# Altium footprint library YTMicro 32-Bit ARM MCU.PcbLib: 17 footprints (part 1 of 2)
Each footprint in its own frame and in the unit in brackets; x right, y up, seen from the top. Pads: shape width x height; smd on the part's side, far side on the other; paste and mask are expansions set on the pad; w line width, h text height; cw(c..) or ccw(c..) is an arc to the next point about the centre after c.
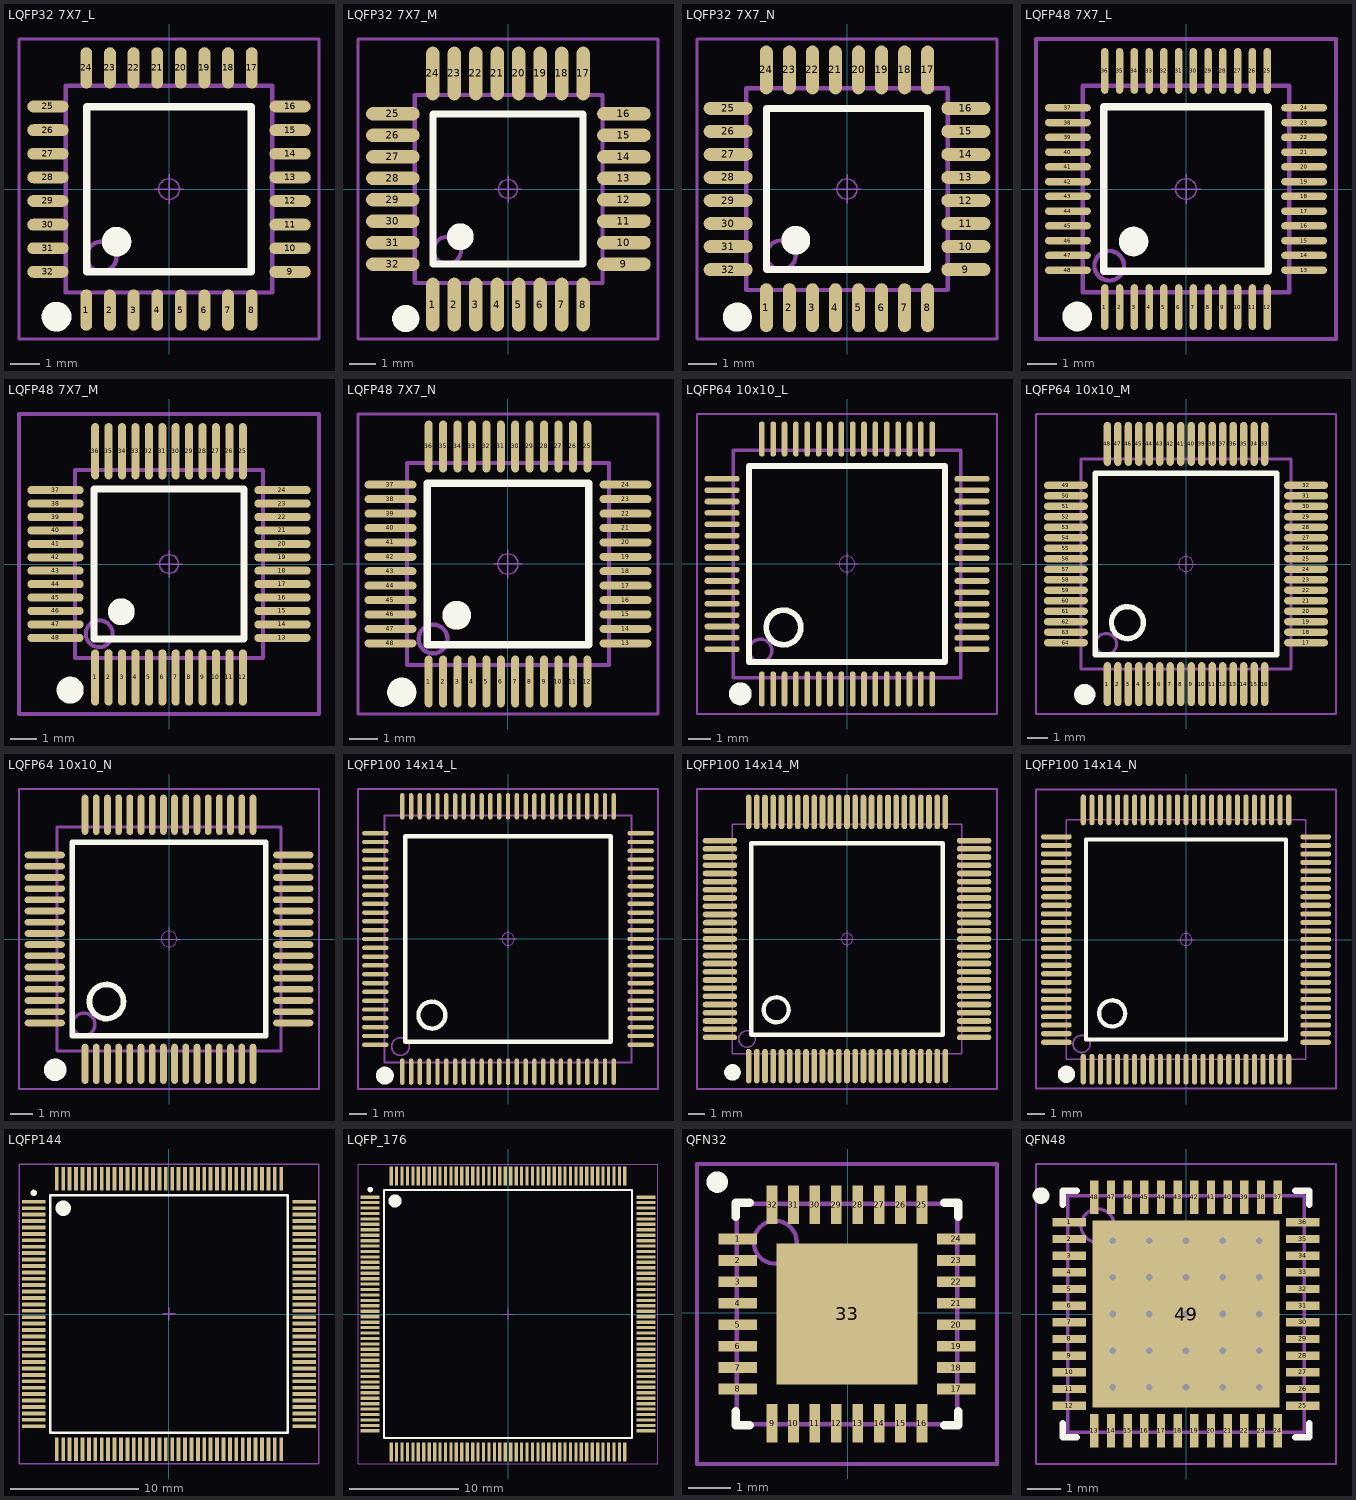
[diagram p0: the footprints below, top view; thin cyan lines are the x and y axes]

## LQFP32 7X7_L [mm]
pads (32):
  oval 0.4x1.4 smd: 1(-2.8,-4.096) 2(-2,-4.096) 3(-1.2,-4.096) 4(-0.4,-4.096) 5(0.4,-4.096) 6(1.2,-4.096) 7(2,-4.096) 8(2.8,-4.096) 17(2.8,4.108) 18(2,4.108) 19(1.2,4.108) 20(0.4,4.108) 21(-0.4,4.108) 22(-1.2,4.108) 23(-2,4.108) 24(-2.8,4.108)
  oval 1.4x0.4 smd: 9(4.102,-2.8) 10(4.102,-2) 11(4.102,-1.2) 12(4.102,-0.4) 13(4.102,0.4) 14(4.102,1.2) 15(4.102,2) 16(4.102,2.8) 25(-4.102,2.8) 26(-4.102,2) 27(-4.102,1.2) 28(-4.102,0.4) 29(-4.102,-0.4) 30(-4.102,-1.2) 31(-4.102,-2) 32(-4.102,-2.8)
Top Overlay:
  circle w0.508: c-3.81,-4.318 r0.25
  circle w0.5: c-1.778,-1.778 r0.25
  lines w0.254: -2.794,-2.794 -2.794,2.794 2.794,2.794 2.794,-2.794 -2.794,-2.794
Mechanical 13:
  circle w0.15: c-2.286,-2.286 r0.508
  lines w0.15: -3.5,-3.5 3.5,-3.5 3.5,3.5 -3.5,3.5 -3.5,-3.5
Mechanical 15:
  circle w0.05: c0,0 r0.35
  lines w0.05: -0.5,0 0.5,0 ; 0,-0.5 0,0.5
  lines w0.1: -5.08,-5.074 5.08,-5.074 5.08,5.086 -5.08,5.086 -5.08,-5.074
3D body "LQFP32-7x7.STEP": height 1.45, standoff 0, extent -4.503,-4.503 4.503,4.503

## LQFP32 7X7_M [mm]
pads (32):
  oval 0.5x2 smd: 1(-2.8,-4.303) 2(-2,-4.303) 3(-1.2,-4.303) 4(-0.4,-4.303) 5(0.4,-4.303) 6(1.2,-4.303) 7(2,-4.303) 8(2.8,-4.303) 17(2.8,4.303) 18(2,4.303) 19(1.2,4.303) 20(0.4,4.303) 21(-0.4,4.303) 22(-1.2,4.303) 23(-2,4.303) 24(-2.8,4.303)
  oval 2x0.5 smd: 9(4.317,-2.8) 10(4.317,-2) 11(4.317,-1.2) 12(4.317,-0.4) 13(4.317,0.4) 14(4.317,1.2) 15(4.317,2) 16(4.317,2.8) 25(-4.289,2.8) 26(-4.289,2) 27(-4.289,1.2) 28(-4.289,0.4) 29(-4.289,-0.4) 30(-4.289,-1.2) 31(-4.289,-2) 32(-4.289,-2.8)
Top Overlay:
  circle w0.5: c-1.778,-1.778 r0.25
  circle w0.508: c-3.81,-4.826 r0.25
  lines w0.254: -2.794,-2.794 2.794,-2.794 2.794,2.794 -2.794,2.794 -2.794,-2.794
Mechanical 13:
  circle w0.15: c-2.26,-2.286 r0.508
  lines w0.15: -3.474,-3.5 3.526,-3.5 3.526,3.5 -3.474,3.5 -3.474,-3.5
Mechanical 15:
  circle w0.05: c0,0 r0.35
  lines w0.05: -0.5,0 0.5,0 ; 0,-0.5 0,0.5
  lines w0.1: -5.588,-5.588 5.588,-5.588 5.588,5.588 -5.588,5.588 -5.588,-5.588
3D body "LQFP32-7x7.STEP": height 1.45, standoff 0, extent -4.503,-4.503 4.503,4.503

## LQFP32 7X7_N [mm]
pads (32):
  oval 0.45x1.7 smd: 1(-2.8,-4.12) 2(-2,-4.12) 3(-1.2,-4.12) 4(-0.4,-4.12) 5(0.4,-4.12) 6(1.2,-4.12) 7(2,-4.12) 8(2.8,-4.12) 17(2.8,4.132) 18(2,4.132) 19(1.2,4.132) 20(0.4,4.132) 21(-0.4,4.132) 22(-1.2,4.132) 23(-2,4.132) 24(-2.8,4.132)
  oval 1.7x0.45 smd: 9(4.126,-2.8) 10(4.126,-2) 11(4.126,-1.2) 12(4.126,-0.4) 13(4.126,0.4) 14(4.126,1.2) 15(4.126,2) 16(4.126,2.8) 25(-4.126,2.8) 26(-4.126,2) 27(-4.126,1.2) 28(-4.126,0.4) 29(-4.126,-0.4) 30(-4.126,-1.2) 31(-4.126,-2) 32(-4.126,-2.8)
Top Overlay:
  circle w0.5: c-1.778,-1.778 r0.25
  circle w0.508: c-3.81,-4.445 r0.25
  lines w0.254: -2.794,-2.794 2.794,-2.794 2.794,2.794 -2.794,2.794 -2.794,-2.794
Mechanical 13:
  circle w0.15: c-2.286,-2.292 r0.508
  lines w0.15: -3.5,-3.506 -3.5,3.494 3.5,3.494 3.5,-3.506 -3.5,-3.506
Mechanical 15:
  circle w0.05: c0,0 r0.35
  lines w0.05: -0.5,0 0.5,0 ; 0,-0.5 0,0.5
  lines w0.1: -5.207,-5.207 -5.207,5.207 5.207,5.207 5.207,-5.207 -5.207,-5.207
3D body "LQFP32-7x7.STEP": height 1.45, standoff 0, extent -4.503,-4.503 4.503,4.503

## LQFP48 7X7_L [mm]
height 1.6
pads (48):
  oval 0.25x1.55 smd: 1(-2.75,-4) 2(-2.25,-4) 3(-1.75,-4) 4(-1.25,-4) 5(-0.75,-4) 6(-0.25,-4) 7(0.25,-4) 8(0.75,-4) 9(1.25,-4) 10(1.75,-4) 11(2.25,-4) 12(2.75,-4) 25(2.75,4) 26(2.25,4) 27(1.75,4) 28(1.25,4) 29(0.75,4) 30(0.25,4) 31(-0.25,4) 32(-0.75,4) 33(-1.25,4) 34(-1.75,4) 35(-2.25,4) 36(-2.75,4)
  oval 1.55x0.25 smd: 13(4,-2.75) 14(4,-2.25) 15(4,-1.75) 16(4,-1.25) 17(4,-0.75) 18(4,-0.25) 19(4,0.25) 20(4,0.75) 21(4,1.25) 22(4,1.75) 23(4,2.25) 24(4,2.75) 37(-4,2.75) 38(-4,2.25) 39(-4,1.75) 40(-4,1.25) 41(-4,0.75) 42(-4,0.25) 43(-4,-0.25) 44(-4,-0.75) 45(-4,-1.25) 46(-4,-1.75) 47(-4,-2.25) 48(-4,-2.75)
Top Overlay:
  circle w0.508: c-3.683,-4.318 r0.25
  circle w0.5: c-1.778,-1.778 r0.25
  lines w0.254: -2.794,-2.794 -2.794,2.794 2.794,2.794 2.794,-2.794 -2.794,-2.794
Mechanical 13:
  circle w0.15: c-2.6,-2.6 r0.5
  lines w0.15: -3.5,-3.5 -3.5,3.5 3.5,3.5 3.5,-3.5 -3.5,-3.5
Mechanical 15:
  circle w0.05: c0,0 r0.35
  lines w0.05: -0.5,0 0.5,0 ; 0,-0.5 0,0.5
  lines w0.15: -5.08,-5.08 -5.08,5.08 5.08,5.08 5.08,-5.08 -5.08,-5.08
3D body "LQFP48-7x7.STEP": height 1.45, standoff 0, extent -4.503,-4.503 4.503,4.503

## LQFP48 7X7_M [mm]
height 1.6
pads (48):
  oval 0.3x2.1 smd: 1(-2.75,-4.227) 2(-2.25,-4.227) 3(-1.75,-4.227) 4(-1.25,-4.227) 5(-0.75,-4.227) 6(-0.25,-4.227) 7(0.25,-4.227) 8(0.75,-4.227) 9(1.25,-4.227) 10(1.75,-4.227) 11(2.25,-4.227) 12(2.75,-4.227) 25(2.75,4.202) 26(2.25,4.202) 27(1.75,4.202) 28(1.25,4.202) 29(0.75,4.202) 30(0.25,4.202) 31(-0.25,4.202) 32(-0.75,4.202) 33(-1.25,4.202) 34(-1.75,4.202) 35(-2.25,4.202) 36(-2.75,4.202)
  oval 2.1x0.3 smd: 13(4.227,-2.75) 14(4.227,-2.25) 15(4.227,-1.75) 16(4.227,-1.25) 17(4.227,-0.75) 18(4.227,-0.25) 19(4.227,0.25) 20(4.227,0.75) 21(4.227,1.25) 22(4.227,1.75) 23(4.227,2.25) 24(4.227,2.75) 37(-4.227,2.75) 38(-4.227,2.25) 39(-4.227,1.75) 40(-4.227,1.25) 41(-4.227,0.75) 42(-4.227,0.25) 43(-4.227,-0.25) 44(-4.227,-0.75) 45(-4.227,-1.25) 46(-4.227,-1.75) 47(-4.227,-2.25) 48(-4.227,-2.75)
Top Overlay:
  circle w0.5: c-1.778,-1.778 r0.25
  circle w0.508: c-3.683,-4.699 r0.25
  lines w0.254: -2.794,-2.794 2.794,-2.794 2.794,2.794 -2.794,2.794 -2.794,-2.794
Mechanical 13:
  circle w0.15: c-2.6,-2.6 r0.5
  lines w0.15: -3.5,-3.5 -3.5,3.5 3.5,3.5 3.5,-3.5 -3.5,-3.5
Mechanical 15:
  circle w0.05: c0,0 r0.35
  lines w0.05: -0.5,0 0.5,0 ; 0,-0.5 0,0.5
  lines w0.15: -5.588,-5.588 -5.588,5.588 5.588,5.588 5.588,-5.588 -5.588,-5.588
3D body "LQFP48-7x7.STEP": height 1.45, standoff 0, extent -4.503,-4.503 4.503,4.503

## LQFP48 7X7_N [mm]
height 1.6
pads (48):
  oval 0.279x1.8 smd: 1(-2.75,-4.075) 2(-2.25,-4.075) 3(-1.75,-4.075) 4(-1.25,-4.075) 5(-0.75,-4.075) 6(-0.25,-4.075) 7(0.25,-4.075) 8(0.75,-4.075) 9(1.25,-4.075) 10(1.75,-4.075) 11(2.25,-4.075) 12(2.75,-4.075) 25(2.75,4.075) 26(2.25,4.075) 27(1.75,4.075) 28(1.25,4.075) 29(0.75,4.075) 30(0.25,4.075) 31(-0.25,4.075) 32(-0.75,4.075) 33(-1.25,4.075) 34(-1.75,4.075) 35(-2.25,4.075) 36(-2.75,4.075)
  oval 1.8x0.279 smd: 13(4.075,-2.75) 14(4.075,-2.25) 15(4.075,-1.75) 16(4.075,-1.25) 17(4.075,-0.75) 18(4.075,-0.25) 19(4.075,0.25) 20(4.075,0.75) 21(4.075,1.25) 22(4.075,1.75) 23(4.075,2.25) 24(4.075,2.75) 37(-4.075,2.75) 38(-4.075,2.25) 39(-4.075,1.75) 40(-4.075,1.25) 41(-4.075,0.75) 42(-4.075,0.25) 43(-4.075,-0.25) 44(-4.075,-0.75) 45(-4.075,-1.25) 46(-4.075,-1.75) 47(-4.075,-2.25) 48(-4.075,-2.75)
Top Overlay:
  circle w0.5: c-1.778,-1.778 r0.25
  circle w0.508: c-3.683,-4.445 r0.25
  lines w0.254: -2.794,-2.794 2.794,-2.794 2.794,2.794 -2.794,2.794 -2.794,-2.794
Mechanical 13:
  circle w0.15: c-2.6,-2.6 r0.5
  lines w0.15: -3.5,-3.5 -3.5,3.5 3.5,3.5 3.5,-3.5 -3.5,-3.5
Mechanical 15:
  circle w0.05: c0,0 r0.35
  lines w0.05: -0.5,0 0.5,0 ; 0,-0.5 0,0.5
  lines w0.1: -5.2,-5.2 5.2,-5.2 5.2,5.2 -5.2,5.2 -5.2,-5.2
3D body "LQFP48-7x7.STEP": height 1.45, standoff 0, extent -4.503,-4.503 4.503,4.503

## LQFP64 10x10_L [mm]
height 1.6
pads (64):
  oval 0.25x1.55 smd: 1(-3.75,-5.5) 2(-3.25,-5.5) 3(-2.75,-5.5) 4(-2.25,-5.5) 5(-1.75,-5.5) 6(-1.25,-5.5) 7(-0.75,-5.5) 8(-0.25,-5.5) 9(0.25,-5.5) 10(0.75,-5.5) 11(1.25,-5.5) 12(1.75,-5.5) 13(2.25,-5.5) 14(2.75,-5.5) 15(3.25,-5.5) 16(3.75,-5.5) 33(3.75,5.5) 34(3.25,5.5) 35(2.75,5.5) 36(2.25,5.5) 37(1.75,5.5) 38(1.25,5.5) 39(0.75,5.5) 40(0.25,5.5) 41(-0.25,5.5) 42(-0.75,5.5) 43(-1.25,5.5) 44(-1.75,5.5) 45(-2.25,5.5) 46(-2.75,5.5) 47(-3.25,5.5) 48(-3.75,5.5)
  oval 1.55x0.25 smd: 17(5.5,-3.75) 18(5.5,-3.25) 19(5.5,-2.75) 20(5.5,-2.25) 21(5.5,-1.75) 22(5.5,-1.25) 23(5.5,-0.75) 24(5.5,-0.25) 25(5.5,0.25) 26(5.5,0.75) 27(5.5,1.25) 28(5.5,1.75) 29(5.5,2.25) 30(5.5,2.75) 31(5.5,3.25) 32(5.5,3.75) 49(-5.499,3.75) 50(-5.499,3.25) 51(-5.499,2.75) 52(-5.499,2.25) 53(-5.499,1.75) 54(-5.499,1.25) 55(-5.499,0.75) 56(-5.499,0.25) 57(-5.499,-0.25) 58(-5.499,-0.75) 59(-5.499,-1.25) 60(-5.499,-1.75) 61(-5.499,-2.25) 62(-5.499,-2.75) 63(-5.499,-3.25) 64(-5.499,-3.75)
Top Overlay:
  circle w0.508: c-4.699,-5.715 r0.25
  circle w0.254: c-2.794,-2.794 r0.762
  lines w0.254: -4.318,-4.318 4.318,-4.318 4.318,4.318 -4.318,4.318 -4.318,-4.318
Mechanical 13:
  circle w0.15: c-3.81,-3.81 r0.5
  lines w0.15: -5,-5 5,-5 5,5 -5,5 -5,-5
Mechanical 15:
  circle w0.05: c0,0 r0.35
  lines w0.05: -0.5,0 0.5,0 ; 0,-0.5 0,0.5
  lines w0.1: -6.604,-6.604 6.604,-6.604 6.604,6.604 -6.604,6.604 -6.604,-6.604
3D body "LQFP64-10x10.STEP": height 1.45, standoff -0.01, extent -6.003,-6.003 6.003,6.003

## LQFP64 10x10_M [mm]
height 1.6
pads (64):
  oval 0.35x2.1 smd: 1(-3.75,-5.727) 2(-3.25,-5.727) 3(-2.75,-5.727) 4(-2.25,-5.727) 5(-1.75,-5.727) 6(-1.25,-5.727) 7(-0.75,-5.727) 8(-0.25,-5.727) 9(0.25,-5.727) 10(0.75,-5.727) 11(1.25,-5.727) 12(1.75,-5.727) 13(2.25,-5.727) 14(2.75,-5.727) 15(3.25,-5.727) 16(3.75,-5.727) 33(3.75,5.727) 34(3.25,5.727) 35(2.75,5.727) 36(2.25,5.727) 37(1.75,5.727) 38(1.25,5.727) 39(0.75,5.727) 40(0.25,5.727) 41(-0.25,5.727) 42(-0.75,5.727) 43(-1.25,5.727) 44(-1.75,5.727) 45(-2.25,5.727) 46(-2.75,5.727) 47(-3.25,5.727) 48(-3.75,5.727)
  oval 2.1x0.35 smd: 17(5.727,-3.75) 18(5.727,-3.25) 19(5.727,-2.75) 20(5.727,-2.25) 21(5.727,-1.75) 22(5.727,-1.25) 23(5.727,-0.75) 24(5.727,-0.25) 25(5.727,0.25) 26(5.727,0.75) 27(5.727,1.25) 28(5.727,1.75) 29(5.727,2.25) 30(5.727,2.75) 31(5.727,3.25) 32(5.727,3.75) 49(-5.727,3.75) 50(-5.727,3.25) 51(-5.727,2.75) 52(-5.727,2.25) 53(-5.727,1.75) 54(-5.727,1.25) 55(-5.727,0.75) 56(-5.727,0.25) 57(-5.727,-0.25) 58(-5.727,-0.75) 59(-5.727,-1.25) 60(-5.727,-1.75) 61(-5.727,-2.25) 62(-5.727,-2.75) 63(-5.727,-3.25) 64(-5.727,-3.75)
Top Overlay:
  circle w0.508: c-4.826,-6.223 r0.25
  circle w0.254: c-2.794,-2.794 r0.762
  lines w0.254: -4.318,-4.318 4.318,-4.318 4.318,4.318 -4.318,4.318 -4.318,-4.318
Mechanical 13:
  circle w0.15: c-3.81,-3.81 r0.5
  lines w0.15: -5,-5 5,-5 5,5 -5,5 -5,-5
Mechanical 15:
  circle w0.05: c0,0 r0.35
  lines w0.05: -0.5,0 0.5,0 ; 0,-0.5 0,0.5
  lines w0.1: -7.15,-7.15 -7.15,7.15 7.15,7.15 7.15,-7.15 -7.15,-7.15
3D body "LQFP64-10x10.STEP": height 1.45, standoff -0.01, extent -6.003,-6.003 6.003,6.003

## LQFP64 10x10_N [mm]
height 1.6
pads (64):
  oval 0.3x1.8 smd: 1(-3.75,-5.575) 2(-3.25,-5.575) 3(-2.75,-5.575) 4(-2.25,-5.575) 5(-1.75,-5.575) 6(-1.25,-5.575) 7(-0.75,-5.575) 8(-0.25,-5.575) 9(0.25,-5.575) 10(0.75,-5.575) 11(1.25,-5.575) 12(1.75,-5.575) 13(2.25,-5.575) 14(2.75,-5.575) 15(3.25,-5.575) 16(3.75,-5.575) 33(3.75,5.55) 34(3.25,5.55) 35(2.75,5.55) 36(2.25,5.55) 37(1.75,5.55) 38(1.25,5.55) 39(0.75,5.55) 40(0.25,5.55) 41(-0.25,5.55) 42(-0.75,5.55) 43(-1.25,5.55) 44(-1.75,5.55) 45(-2.25,5.55) 46(-2.75,5.55) 47(-3.25,5.55) 48(-3.75,5.55)
  oval 1.8x0.3 smd: 17(5.55,-3.75) 18(5.55,-3.25) 19(5.55,-2.75) 20(5.55,-2.25) 21(5.55,-1.75) 22(5.55,-1.25) 23(5.55,-0.75) 24(5.55,-0.25) 25(5.55,0.25) 26(5.55,0.75) 27(5.55,1.25) 28(5.55,1.75) 29(5.55,2.25) 30(5.55,2.75) 31(5.55,3.25) 32(5.55,3.75) 49(-5.55,3.75) 50(-5.55,3.25) 51(-5.55,2.75) 52(-5.55,2.25) 53(-5.55,1.75) 54(-5.55,1.25) 55(-5.55,0.75) 56(-5.55,0.25) 57(-5.55,-0.25) 58(-5.55,-0.75) 59(-5.55,-1.25) 60(-5.55,-1.75) 61(-5.55,-2.25) 62(-5.55,-2.75) 63(-5.55,-3.25) 64(-5.55,-3.75)
Top Overlay:
  circle w0.254: c-2.794,-2.794 r0.762
  circle w0.508: c-5.08,-5.842 r0.25
  lines w0.254: -4.318,-4.318 -4.318,4.318 4.318,4.318 4.318,-4.318 -4.318,-4.318
Mechanical 13:
  circle w0.15: c-3.81,-3.81 r0.5
  lines w0.15: -5,-5 -5,5 5,5 5,-5 -5,-5
Mechanical 15:
  circle w0.05: c0,0 r0.35
  lines w0.05: -0.5,0 0.5,0 ; 0,-0.5 0,0.5
  lines w0.1: -6.7,-6.7 6.7,-6.7 6.7,6.7 -6.7,6.7 -6.7,-6.7
3D body "LQFP64-10x10.STEP": height 1.45, standoff -0.01, extent -6.003,-6.003 6.003,6.003

## LQFP100 14x14_L [mm]
height 1.6
pads (100):
  oval 0.25x1.5 smd: 1(-6,-7.525) 2(-5.5,-7.525) 3(-5,-7.525) 4(-4.5,-7.525) 5(-4,-7.525) 6(-3.5,-7.525) 7(-3,-7.525) 8(-2.5,-7.525) 9(-2,-7.525) 10(-1.5,-7.525) 11(-1,-7.525) 12(-0.5,-7.525) 13(0,-7.525) 14(0.5,-7.525) 15(1,-7.525) 16(1.5,-7.525) 17(2,-7.525) 18(2.5,-7.525) 19(3,-7.525) 20(3.5,-7.525) 21(4,-7.525) 22(4.5,-7.525) 23(5,-7.525) 24(5.5,-7.525) 25(6,-7.525) 51(6,7.525) 52(5.5,7.525) 53(5,7.525) 54(4.5,7.525) 55(4,7.525) 56(3.5,7.525) 57(3,7.525) 58(2.5,7.525) 59(2,7.525) 60(1.5,7.525) 61(1,7.525) 62(0.5,7.525) 63(0,7.525) 64(-0.5,7.525) 65(-1,7.525) 66(-1.5,7.525) 67(-2,7.525) 68(-2.5,7.525) 69(-3,7.525) 70(-3.5,7.525) 71(-4,7.525) 72(-4.5,7.525) 73(-5,7.525) 74(-5.5,7.525) 75(-6,7.525)
  oval 1.5x0.25 smd: 26(7.525,-6) 27(7.525,-5.5) 28(7.525,-5) 29(7.525,-4.5) 30(7.525,-4) 31(7.525,-3.5) 32(7.525,-3) 33(7.525,-2.5) 34(7.525,-2) 35(7.525,-1.5) 36(7.525,-1) 37(7.525,-0.5) 38(7.525,0) 39(7.525,0.5) 40(7.525,1) 41(7.525,1.5) 42(7.525,2) 43(7.525,2.5) 44(7.525,3) 45(7.525,3.5) 46(7.525,4) 47(7.525,4.5) 48(7.525,5) 49(7.525,5.5) 50(7.525,6) 76(-7.525,6) 77(-7.525,5.5) 78(-7.525,5) 79(-7.525,4.5) 80(-7.525,4) 81(-7.525,3.5) 82(-7.525,3) 83(-7.525,2.5) 84(-7.525,2) 85(-7.525,1.5) 86(-7.525,1) 87(-7.525,0.5) 88(-7.525,0) 89(-7.525,-0.5) 90(-7.525,-1) 91(-7.525,-1.5) 92(-7.525,-2) 93(-7.525,-2.5) 94(-7.525,-3) 95(-7.525,-3.5) 96(-7.525,-4) 97(-7.525,-4.5) 98(-7.525,-5) 99(-7.525,-5.5) 100(-7.525,-6)
Top Overlay:
  circle w0.508: c-6.985,-7.747 r0.25
  circle w0.254: c-4.318,-4.318 r0.762
  lines w0.254: -5.842,-5.842 -5.842,5.842 5.842,5.842 5.842,-5.842 -5.842,-5.842
Mechanical 13:
  circle w0.1: c-6.1,-6.1 r0.5
  lines w0.1: -7,-7 -7,7 7,7 7,-7 -7,-7
Mechanical 15:
  circle w0.05: c0,0 r0.35
  lines w0.05: -0.5,0 0.5,0 ; 0,-0.5 0,0.5
  lines w0.1: -8.509,-8.509 -8.509,8.509 8.509,8.509 8.509,-8.509 -8.509,-8.509
3D body "LQFP100-14x14.STEP": height 1.45, standoff -0.01, extent -8.003,-8.003 8.003,8.003

## LQFP100 14x14_M [mm]
height 1.6
pads (100):
  oval 0.35x2.1 smd: 1(-6,-7.747) 2(-5.5,-7.747) 3(-5,-7.747) 4(-4.5,-7.747) 5(-4,-7.747) 6(-3.5,-7.747) 7(-3,-7.747) 8(-2.5,-7.747) 9(-2,-7.747) 10(-1.5,-7.747) 11(-1,-7.747) 12(-0.5,-7.747) 13(0,-7.747) 14(0.5,-7.747) 15(1,-7.747) 16(1.5,-7.747) 17(2,-7.747) 18(2.5,-7.747) 19(3,-7.747) 20(3.5,-7.747) 21(4,-7.747) 22(4.5,-7.747) 23(5,-7.747) 24(5.5,-7.747) 25(6,-7.747) 51(6,7.758) 52(5.5,7.758) 53(5,7.758) 54(4.5,7.758) 55(4,7.758) 56(3.5,7.758) 57(3,7.758) 58(2.5,7.758) 59(2,7.758) 60(1.5,7.758) 61(1,7.758) 62(0.5,7.758) 63(0,7.758) 64(-0.5,7.758) 65(-1,7.758) 66(-1.5,7.758) 67(-2,7.758) 68(-2.5,7.758) 69(-3,7.758) 70(-3.5,7.758) 71(-4,7.758) 72(-4.5,7.758) 73(-5,7.758) 74(-5.5,7.758) 75(-6,7.758)
  oval 2.1x0.35 smd: 26(7.752,-5.994) 27(7.752,-5.494) 28(7.752,-4.994) 29(7.752,-4.494) 30(7.752,-3.994) 31(7.752,-3.494) 32(7.752,-2.994) 33(7.752,-2.494) 34(7.752,-1.994) 35(7.752,-1.494) 36(7.752,-0.994) 37(7.752,-0.494) 38(7.752,0.006) 39(7.752,0.506) 40(7.752,1.006) 41(7.752,1.506) 42(7.752,2.006) 43(7.752,2.506) 44(7.752,3.006) 45(7.752,3.506) 46(7.752,4.006) 47(7.752,4.506) 48(7.752,5.006) 49(7.752,5.506) 50(7.752,6.006) 76(-7.752,6.006) 77(-7.752,5.506) 78(-7.752,5.006) 79(-7.752,4.506) 80(-7.752,4.006) 81(-7.752,3.506) 82(-7.752,3.006) 83(-7.752,2.506) 84(-7.752,2.006) 85(-7.752,1.506) 86(-7.752,1.006) 87(-7.752,0.506) 88(-7.752,0.006) 89(-7.752,-0.494) 90(-7.752,-0.994) 91(-7.752,-1.494) 92(-7.752,-1.994) 93(-7.752,-2.494) 94(-7.752,-2.994) 95(-7.752,-3.494) 96(-7.752,-3.994) 97(-7.752,-4.494) 98(-7.752,-4.994) 99(-7.752,-5.494) 100(-7.752,-5.994)
Top Overlay:
  circle w0.254: c-4.318,-4.312 r0.762
  circle w0.508: c-6.985,-8.128 r0.25
  lines w0.254: -5.842,-5.836 5.842,-5.836 5.842,5.848 -5.842,5.848 -5.842,-5.836
Mechanical 13:
  circle w0.1: c-6.1,-6.094 r0.5
  lines w0.1: -7,-6.994 -7,7.006 7,7.006 7,-6.994 -7,-6.994
Mechanical 15:
  circle w0.05: c0,0.006 r0.35
  lines w0.05: -0.5,0.006 0.5,0.006 ; 0,-0.494 0,0.506
  lines w0.1: -9.15,-9.144 -9.15,9.156 9.15,9.156 9.15,-9.144 -9.15,-9.144
3D body "LQFP100-14x14.STEP": height 1.45, standoff -0.01, extent -8.003,-7.997 8.003,8.009

## LQFP100 14x14_N [mm]
height 1.6
pads (100):
  oval 0.3x1.8 smd: 1(-6,-7.575) 2(-5.5,-7.575) 3(-5,-7.575) 4(-4.5,-7.575) 5(-4,-7.575) 6(-3.5,-7.575) 7(-3,-7.575) 8(-2.5,-7.575) 9(-2,-7.575) 10(-1.5,-7.575) 11(-1,-7.575) 12(-0.5,-7.575) 13(0,-7.575) 14(0.5,-7.575) 15(1,-7.575) 16(1.5,-7.575) 17(2,-7.575) 18(2.5,-7.575) 19(3,-7.575) 20(3.5,-7.575) 21(4,-7.575) 22(4.5,-7.575) 23(5,-7.575) 24(5.5,-7.575) 25(6,-7.575) 51(6,7.575) 52(5.5,7.575) 53(5,7.575) 54(4.5,7.575) 55(4,7.575) 56(3.5,7.575) 57(3,7.575) 58(2.5,7.575) 59(2,7.575) 60(1.5,7.575) 61(1,7.575) 62(0.5,7.575) 63(0,7.575) 64(-0.5,7.575) 65(-1,7.575) 66(-1.5,7.575) 67(-2,7.575) 68(-2.5,7.575) 69(-3,7.575) 70(-3.5,7.575) 71(-4,7.575) 72(-4.5,7.575) 73(-5,7.575) 74(-5.5,7.575) 75(-6,7.575)
  oval 1.8x0.3 smd: 26(7.576,-6) 27(7.576,-5.5) 28(7.576,-5) 29(7.576,-4.5) 30(7.576,-4) 31(7.576,-3.5) 32(7.576,-3) 33(7.576,-2.5) 34(7.576,-2) 35(7.576,-1.5) 36(7.576,-1) 37(7.576,-0.5) 38(7.576,0) 39(7.576,0.5) 40(7.576,1) 41(7.576,1.5) 42(7.576,2) 43(7.576,2.5) 44(7.576,3) 45(7.576,3.5) 46(7.576,4) 47(7.576,4.5) 48(7.576,5) 49(7.576,5.5) 50(7.576,6) 76(-7.575,6) 77(-7.575,5.5) 78(-7.575,5) 79(-7.575,4.5) 80(-7.575,4) 81(-7.575,3.5) 82(-7.575,3) 83(-7.575,2.5) 84(-7.575,2) 85(-7.575,1.5) 86(-7.575,1) 87(-7.575,0.5) 88(-7.575,0) 89(-7.575,-0.5) 90(-7.575,-1) 91(-7.575,-1.5) 92(-7.575,-2) 93(-7.575,-2.5) 94(-7.575,-3) 95(-7.575,-3.5) 96(-7.575,-4) 97(-7.575,-4.5) 98(-7.575,-5) 99(-7.575,-5.5) 100(-7.575,-6)
Top Overlay:
  circle w0.508: c-6.985,-7.874 r0.25
  circle w0.254: c-4.318,-4.318 r0.762
  lines w0.254: -5.842,-5.842 -5.842,5.842 5.842,5.842 5.842,-5.842 -5.842,-5.842
Mechanical 13:
  circle w0.1: c-6.1,-6.1 r0.5
  lines w0.1: -7,-7 7,-7 7,7 -7,7 -7,-7
Mechanical 15:
  circle w0.05: c0,0 r0.35
  lines w0.05: -0.5,0 0.5,0 ; 0,-0.5 0,0.5
  lines w0.1: -8.763,-8.7 8.763,-8.7 8.763,8.763 -8.763,8.763 -8.763,-8.7
3D body "LQFP100-14x14.STEP": height 1.45, standoff -0.01, extent -8.003,-8.003 8.003,8.003

## LQFP144 [mm] "144-Pin Thin Quad Flat Pack 0.5 mm Pitch, IPC Medium Density"
height 1.6
pads (144):
  rect 1.8x0.3 smd: 1(-10.55,8.75) 2(-10.55,8.25) 3(-10.55,7.75) 4(-10.55,7.25) 5(-10.55,6.75) 6(-10.55,6.25) 7(-10.55,5.75) 8(-10.55,5.25) 9(-10.55,4.75) 10(-10.55,4.25) 11(-10.55,3.75) 12(-10.55,3.25) 13(-10.55,2.75) 14(-10.55,2.25) 15(-10.55,1.75) 16(-10.55,1.25) 17(-10.55,0.75) 18(-10.55,0.25) 19(-10.55,-0.25) 20(-10.55,-0.75) 21(-10.55,-1.25) 22(-10.55,-1.75) 23(-10.55,-2.25) 24(-10.55,-2.75) 25(-10.55,-3.25) 26(-10.55,-3.75) 27(-10.55,-4.25) 28(-10.55,-4.75) 29(-10.55,-5.25) 30(-10.55,-5.75) 31(-10.55,-6.25) 32(-10.55,-6.75) 33(-10.55,-7.25) 34(-10.55,-7.75) 35(-10.55,-8.25) 36(-10.55,-8.75) 73(10.55,-8.75) 74(10.55,-8.25) 75(10.55,-7.75) 76(10.55,-7.25) 77(10.55,-6.75) 78(10.55,-6.25) 79(10.55,-5.75) 80(10.55,-5.25) 81(10.55,-4.75) 82(10.55,-4.25) 83(10.55,-3.75) 84(10.55,-3.25) 85(10.55,-2.75) 86(10.55,-2.25) 87(10.55,-1.75) 88(10.55,-1.25) 89(10.55,-0.75) 90(10.55,-0.25) 91(10.55,0.25) 92(10.55,0.75) 93(10.55,1.25) 94(10.55,1.75) 95(10.55,2.25) 96(10.55,2.75) 97(10.55,3.25) 98(10.55,3.75) 99(10.55,4.25) 100(10.55,4.75) 101(10.55,5.25) 102(10.55,5.75) 103(10.55,6.25) 104(10.55,6.75) 105(10.55,7.25) 106(10.55,7.75) 107(10.55,8.25) 108(10.55,8.75)
  rect 0.3x1.8 smd: 37(-8.75,-10.55) 38(-8.25,-10.55) 39(-7.75,-10.55) 40(-7.25,-10.55) 41(-6.75,-10.55) 42(-6.25,-10.55) 43(-5.75,-10.55) 44(-5.25,-10.55) 45(-4.75,-10.55) 46(-4.25,-10.55) 47(-3.75,-10.55) 48(-3.25,-10.55) 49(-2.75,-10.55) 50(-2.25,-10.55) 51(-1.75,-10.55) 52(-1.25,-10.55) 53(-0.75,-10.55) 54(-0.25,-10.55) 55(0.25,-10.55) 56(0.75,-10.55) 57(1.25,-10.55) 58(1.75,-10.55) 59(2.25,-10.55) 60(2.75,-10.55) 61(3.25,-10.55) 62(3.75,-10.55) 63(4.25,-10.55) 64(4.75,-10.55) 65(5.25,-10.55) 66(5.75,-10.55) 67(6.25,-10.55) 68(6.75,-10.55) 69(7.25,-10.55) 70(7.75,-10.55) 71(8.25,-10.55) 72(8.75,-10.55) 109(8.75,10.55) 110(8.25,10.55) 111(7.75,10.55) 112(7.25,10.55) 113(6.75,10.55) 114(6.25,10.55) 115(5.75,10.55) 116(5.25,10.55) 117(4.75,10.55) 118(4.25,10.55) 119(3.75,10.55) 120(3.25,10.55) 121(2.75,10.55) 122(2.25,10.55) 123(1.75,10.55) 124(1.25,10.55) 125(0.75,10.55) 126(0.25,10.55) 127(-0.25,10.55) 128(-0.75,10.55) 129(-1.25,10.55) 130(-1.75,10.55) 131(-2.25,10.55) 132(-2.75,10.55) 133(-3.25,10.55) 134(-3.75,10.55) 135(-4.25,10.55) 136(-4.75,10.55) 137(-5.25,10.55) 138(-5.75,10.55) 139(-6.25,10.55) 140(-6.75,10.55) 141(-7.25,10.55) 142(-7.75,10.55) 143(-8.25,10.55) 144(-8.75,10.55)
Top Overlay:
  circle w0.25: c-10.55,9.45 r0.125
  circle w0.6: c-8.25,8.25 r0.3
  lines w0.2: -9.25,-9.25 -9.25,9.25 9.25,9.25 9.25,-9.25 -9.25,-9.25
Mechanical 15:
  lines w0.1: -0.5,0 0.5,0 ; 0,-0.5 0,0.5 ; -11.7,-11.7 -11.7,11.7 11.7,11.7 11.7,-11.7 -11.7,-11.7
3D body "User Library-LQFP144-3.STEP": height 1.8, standoff -0.09, extent -11.101,-11.101 11.101,11.101

## LQFP_176 [mm] "LQFP, 176-Leads, Body 26.4x26.4mm (max), Pitch 0.50mm, IPC Medium Density"
height 1.6
pads (176):
  rect 1.75x0.3 smd: 1(-12.675,10.75) 2(-12.675,10.25) 3(-12.675,9.75) 4(-12.675,9.25) 5(-12.675,8.75) 6(-12.675,8.25) 7(-12.675,7.75) 8(-12.675,7.25) 9(-12.675,6.75) 10(-12.675,6.25) 11(-12.675,5.75) 12(-12.675,5.25) 13(-12.675,4.75) 14(-12.675,4.25) 15(-12.675,3.75) 16(-12.675,3.25) 17(-12.675,2.75) 18(-12.675,2.25) 19(-12.675,1.75) 20(-12.675,1.25) 21(-12.675,0.75) 22(-12.675,0.25) 23(-12.675,-0.25) 24(-12.675,-0.75) 25(-12.675,-1.25) 26(-12.675,-1.75) 27(-12.675,-2.25) 28(-12.675,-2.75) 29(-12.675,-3.25) 30(-12.675,-3.75) 31(-12.675,-4.25) 32(-12.675,-4.75) 33(-12.675,-5.25) 34(-12.675,-5.75) 35(-12.675,-6.25) 36(-12.675,-6.75) 37(-12.675,-7.25) 38(-12.675,-7.75) 39(-12.675,-8.25) 40(-12.675,-8.75) 41(-12.675,-9.25) 42(-12.675,-9.75) 43(-12.675,-10.25) 44(-12.675,-10.75) 89(12.675,-10.75) 90(12.675,-10.25) 91(12.675,-9.75) 92(12.675,-9.25) 93(12.675,-8.75) 94(12.675,-8.25) 95(12.675,-7.75) 96(12.675,-7.25) 97(12.675,-6.75) 98(12.675,-6.25) 99(12.675,-5.75) 100(12.675,-5.25) 101(12.675,-4.75) 102(12.675,-4.25) 103(12.675,-3.75) 104(12.675,-3.25) 105(12.675,-2.75) 106(12.675,-2.25) 107(12.675,-1.75) 108(12.675,-1.25) 109(12.675,-0.75) 110(12.675,-0.25) 111(12.675,0.25) 112(12.675,0.75) 113(12.675,1.25) 114(12.675,1.75) 115(12.675,2.25) 116(12.675,2.75) 117(12.675,3.25) 118(12.675,3.75) 119(12.675,4.25) 120(12.675,4.75) 121(12.675,5.25) 122(12.675,5.75) 123(12.675,6.25) 124(12.675,6.75) 125(12.675,7.25) 126(12.675,7.75) 127(12.675,8.25) 128(12.675,8.75) 129(12.675,9.25) 130(12.675,9.75) 131(12.675,10.25) 132(12.675,10.75)
  rect 0.3x1.75 smd: 45(-10.75,-12.675) 46(-10.25,-12.675) 47(-9.75,-12.675) 48(-9.25,-12.675) 49(-8.75,-12.675) 50(-8.25,-12.675) 51(-7.75,-12.675) 52(-7.25,-12.675) 53(-6.75,-12.675) 54(-6.25,-12.675) 55(-5.75,-12.675) 56(-5.25,-12.675) 57(-4.75,-12.675) 58(-4.25,-12.675) 59(-3.75,-12.675) 60(-3.25,-12.675) 61(-2.75,-12.675) 62(-2.25,-12.675) 63(-1.75,-12.675) 64(-1.25,-12.675) 65(-0.75,-12.675) 66(-0.25,-12.675) 67(0.25,-12.675) 68(0.75,-12.675) 69(1.25,-12.675) 70(1.75,-12.675) 71(2.25,-12.675) 72(2.75,-12.675) 73(3.25,-12.675) 74(3.75,-12.675) 75(4.25,-12.675) 76(4.75,-12.675) 77(5.25,-12.675) 78(5.75,-12.675) 79(6.25,-12.675) 80(6.75,-12.675) 81(7.25,-12.675) 82(7.75,-12.675) 83(8.25,-12.675) 84(8.75,-12.675) 85(9.25,-12.675) 86(9.75,-12.675) 87(10.25,-12.675) 88(10.75,-12.675) 133(10.75,12.675) 134(10.25,12.675) 135(9.75,12.675) 136(9.25,12.675) 137(8.75,12.675) 138(8.25,12.675) 139(7.75,12.675) 140(7.25,12.675) 141(6.75,12.675) 142(6.25,12.675) 143(5.75,12.675) 144(5.25,12.675) 145(4.75,12.675) 146(4.25,12.675) 147(3.75,12.675) 148(3.25,12.675) 149(2.75,12.675) 150(2.25,12.675) 151(1.75,12.675) 152(1.25,12.675) 153(0.75,12.675) 154(0.25,12.675) 155(-0.25,12.675) 156(-0.75,12.675) 157(-1.25,12.675) 158(-1.75,12.675) 159(-2.25,12.675) 160(-2.75,12.675) 161(-3.25,12.675) 162(-3.75,12.675) 163(-4.25,12.675) 164(-4.75,12.675) 165(-5.25,12.675) 166(-5.75,12.675) 167(-6.25,12.675) 168(-6.75,12.675) 169(-7.25,12.675) 170(-7.75,12.675) 171(-8.25,12.675) 172(-8.75,12.675) 173(-9.25,12.675) 174(-9.75,12.675) 175(-10.25,12.675) 176(-10.75,12.675)
Top Overlay:
  circle w0.6: c-10.4,10.4 r0.3
  circle w0.25: c-12.675,11.45 r0.125
  lines w0.2: -11.4,-11.4 11.4,-11.4 11.4,11.4 -11.4,11.4 -11.4,-11.4
Mechanical 15:
  lines w0.1: -0.5,0 0.5,0 ; 0,-0.5 0,0.5 ; -13.8,-13.8 13.8,-13.8 13.8,13.8 -13.8,13.8 -13.8,-13.8
3D body "User Library-LQFP176-0_5.step": height 1.58, standoff 0.01, extent -12.886,-12.886 12.886,12.886

## QFN32 [mm]
height 0.381
pads (33):
  rect 0.9x0.25 smd: 1(-2.57,1.72) 2(-2.57,1.22) 3(-2.57,0.72) 4(-2.57,0.22) 5(-2.57,-0.28) 6(-2.57,-0.78) 7(-2.57,-1.28) 8(-2.57,-1.78) 17(2.53,-1.78) 18(2.53,-1.28) 19(2.53,-0.78) 20(2.53,-0.28) 21(2.53,0.22) 22(2.53,0.72) 23(2.53,1.22) 24(2.53,1.72)
  rect 0.25x0.9 smd: 9(-1.77,-2.58) 10(-1.27,-2.58) 11(-0.77,-2.58) 12(-0.27,-2.58) 13(0.23,-2.58) 14(0.73,-2.58) 15(1.23,-2.58) 16(1.73,-2.58) 25(1.73,2.52) 26(1.23,2.52) 27(0.73,2.52) 28(0.23,2.52) 29(-0.27,2.52) 30(-0.77,2.52) 31(-1.27,2.52) 32(-1.77,2.52)
  rect 3.3x3.3 smd: 33(-0.02,-0.03)
Top Overlay:
  circle w0.25: c-3.048,3.048 r0.125
  lines w0.2: -2.62,-2.305 -2.62,-2.63 -2.295,-2.63 ; -2.62,2.245 -2.62,2.57 -2.295,2.57 ; 2.255,-2.63 2.58,-2.63 2.58,-2.305 ; 2.255,2.57 2.58,2.57 2.58,2.245
Mechanical 13:
  circle w0.1: c-1.695,1.645 r0.5
  lines w0.1: -2.595,-2.605 -2.595,2.545 2.555,2.545 2.555,-2.605 -2.595,-2.605
Mechanical 15:
  lines w0.1: -0.52,-0.03 0.48,-0.03 ; -0.02,-0.53 -0.02,0.47 ; -3.52,-3.53 -3.52,3.47 3.48,3.47 3.48,-3.53 -3.52,-3.53
3D body "User Library-QFN32-1.step": height 0.9, standoff -0.03, extent -2.52,-2.53 2.481,2.47

## QFN48 [mm] "QFN, 48-Leads, Body 7.1x7.1mm, Pitch 0.5mm, Thermal Pad 5.6x5.6mm, IPC Low Density"
height 0.6
pads (49):
  rect 1x0.25 smd: 1(-3.5,2.75) 2(-3.5,2.25) 3(-3.5,1.75) 4(-3.5,1.25) 5(-3.5,0.75) 6(-3.5,0.25) 7(-3.5,-0.25) 8(-3.5,-0.75) 9(-3.5,-1.25) 10(-3.5,-1.75) 11(-3.5,-2.25) 12(-3.5,-2.75) 25(3.5,-2.75) 26(3.5,-2.25) 27(3.5,-1.75) 28(3.5,-1.25) 29(3.5,-0.75) 30(3.5,-0.25) 31(3.5,0.25) 32(3.5,0.75) 33(3.5,1.25) 34(3.5,1.75) 35(3.5,2.25) 36(3.5,2.75)
  rect 0.25x1 smd: 13(-2.75,-3.5) 14(-2.25,-3.5) 15(-1.75,-3.5) 16(-1.25,-3.5) 17(-0.75,-3.5) 18(-0.25,-3.5) 19(0.25,-3.5) 20(0.75,-3.5) 21(1.25,-3.5) 22(1.75,-3.5) 23(2.25,-3.5) 24(2.75,-3.5) 37(2.75,3.5) 38(2.25,3.5) 39(1.75,3.5) 40(1.25,3.5) 41(0.75,3.5) 42(0.25,3.5) 43(-0.25,3.5) 44(-0.75,3.5) 45(-1.25,3.5) 46(-1.75,3.5) 47(-2.25,3.5) 48(-2.75,3.5)
  rect 5.6x5.6 smd: 49(0,0)
via -2.2,2.2 diameter 0.5 hole 0.2
via -1.1,2.2 diameter 0.5 hole 0.2
via 0,2.2 diameter 0.5 hole 0.2
via 1.1,2.2 diameter 0.5 hole 0.2
via 2.2,2.2 diameter 0.5 hole 0.2
via -2.2,1.1 diameter 0.5 hole 0.2
via -1.1,1.1 diameter 0.5 hole 0.2
via 0,1.1 diameter 0.5 hole 0.2
via 1.1,1.1 diameter 0.5 hole 0.2
via 2.2,1.1 diameter 0.5 hole 0.2
via -2.2,0 diameter 0.5 hole 0.2
via -1.1,0 diameter 0.5 hole 0.2
via 0,0 diameter 0.5 hole 0.2
via 1.1,0 diameter 0.5 hole 0.2
via 2.2,0 diameter 0.5 hole 0.2
via -2.2,-1.1 diameter 0.5 hole 0.2
via -1.1,-1.1 diameter 0.5 hole 0.2
via 0,-1.1 diameter 0.5 hole 0.2
via 1.1,-1.1 diameter 0.5 hole 0.2
via 2.2,-1.1 diameter 0.5 hole 0.2
via -2.2,-2.2 diameter 0.5 hole 0.2
via -1.1,-2.2 diameter 0.5 hole 0.2
via 0,-2.2 diameter 0.5 hole 0.2
via 1.1,-2.2 diameter 0.5 hole 0.2
via 2.2,-2.2 diameter 0.5 hole 0.2
Top Overlay:
  circle w0.25: c-4.35,3.55 r0.125
  lines w0.2: -3.7,-3.275 -3.7,-3.7 -3.275,-3.7 ; -3.7,3.275 -3.7,3.7 -3.275,3.7 ; 3.275,-3.7 3.7,-3.7 3.7,-3.275 ; 3.275,3.7 3.7,3.7 3.7,3.275
Mechanical 13:
  circle w0.1: c-2.65,2.65 r0.5
  lines w0.1: -3.55,-3.55 -3.55,3.55 3.55,3.55 3.55,-3.55 -3.55,-3.55
Mechanical 15:
  lines w0.05: -4.5,-4.5 -4.5,4.5 4.5,4.5 4.5,-4.5 -4.5,-4.5
  lines w0.1: -0.5,0 0.5,0 ; 0,-0.5 0,0.5
3D body: height 0.6, standoff 0, extent -3.55,-3.55 3.55,3.55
